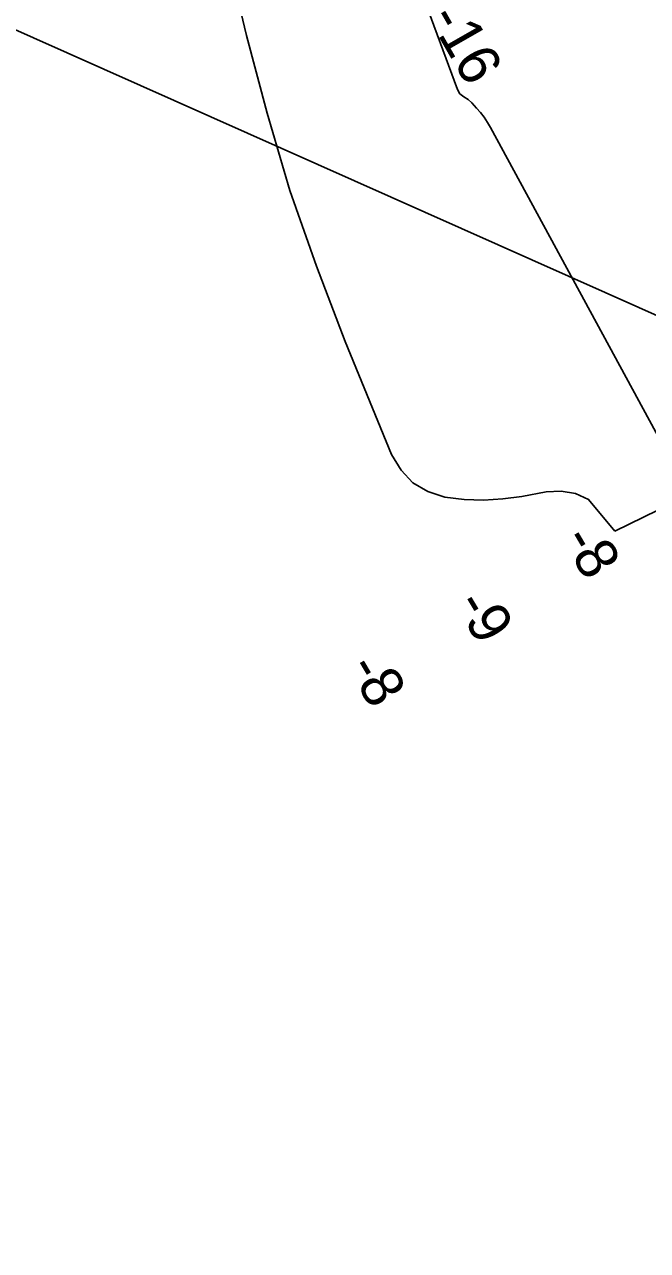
# Model space of a CAD drawing. Extents: x 3972907 to 3994831, y 172639 to 190852.
# Drawn here: x 3982193 to 3982691, y 184038 to 185019 of the extents above; entities that cross this region are included whole.
import ezdxf

# ---------------------------------------------------------------- set-up
doc = ezdxf.new("R2010")
doc.units = 0
for name, color, linetype in [('V-RIVR-JETY', 7, 'Continuous'), ('V-RIVR-RANG', 7, 'Continuous'), ('V-TOPO-DPTH', 7, 'Continuous'), ('V-TOPO-MINR', 7, 'Continuous')]:
    doc.layers.add(name, color=color, linetype=linetype)

msp = doc.modelspace()

# ---------------------------------------------------------------- linework, layer by layer
at = {"layer": 'V-RIVR-JETY'}
msp.add_spline([(3980663.75, 188142.49), (3980923.3, 187897.84), (3981219.12, 187593.73), (3981381.55, 187411.23), (3981548.76, 187223.47), (3981745.95, 186997.4), (3981995.88, 186703.14), (3982287.95, 186350.33), (3982495.82, 186079.54), (3982762.84, 185654.69), (3982971.02, 185292.43), (3983111.24, 185037.47), (3983200.02, 184881.79), (3983229.93, 184826.38)], degree=3, dxfattribs=at)
at = {"layer": 'V-RIVR-RANG'}
msp.add_lwpolyline([(3982021.28, 185087.72), (3990774.16, 181190.72)], dxfattribs=at)
at = {"layer": 'V-TOPO-DPTH'}
for points in [[(3982299.91, 185303.54), (3982370.1, 185010.32), (3982386.54, 184948.03), (3982404.87, 184886.34), (3982426.03, 184825.57), (3982449.07, 184765.41), (3982486.14, 184674.94), (3982493.72, 184662.53), (3982503.07, 184652.35), (3982515.08, 184645.5), (3982528.86, 184640.87), (3982544.28, 184639.14), (3982559.69, 184638.49), (3982575.08, 184639.45), (3982590.47, 184641.5), (3982609.81, 184645.12), (3982621.84, 184645.56), (3982633.24, 184643.88), (3982643.7, 184639.02), (3982664.77, 184613.75)], [(3982664.77, 184613.75), (3983207.36, 184878.75)]]:
    msp.add_lwpolyline(points, dxfattribs=at)
at = {"layer": 'V-TOPO-MINR'}
for points in [[(3982299.91, 185303.54), (3982370.1, 185010.32), (3982386.54, 184948.03), (3982404.87, 184886.34), (3982426.03, 184825.57), (3982449.07, 184765.41), (3982486.14, 184674.94), (3982493.72, 184662.53), (3982503.07, 184652.35), (3982515.08, 184645.5), (3982528.86, 184640.87), (3982544.28, 184639.14), (3982559.69, 184638.49), (3982575.08, 184639.45), (3982590.47, 184641.5), (3982609.81, 184645.12), (3982621.84, 184645.56), (3982633.24, 184643.88), (3982643.7, 184639.02), (3982664.77, 184613.75)], [(3982510.96, 185043.07), (3982538.86, 184967.03), (3982540.84, 184963.67), (3982543.89, 184961.24), (3982547.3, 184959.03), (3982550.3, 184956.3), (3982554.12, 184952.21), (3982557.28, 184948.56), (3982560.25, 184944.76), (3982562.91, 184940.75), (3982565.37, 184936.6), (3982716.34, 184658.45)]]:
    msp.add_lwpolyline(points, dxfattribs=at)

# ---------------------------------------------------------------- texts
at = {"layer": 'V-RIVR-RANG'}
for s, rotation, p in [('-16', 299.78, (3982515.2, 185024.32)), ('-8', 300.73833, (3982621.91, 184606.92)), ('-9', 300.73833, (3982536.29, 184555.26)), ('-8', 300.73833, (3982450.26, 184504.28))]:
    msp.add_text(s, height=33.5, rotation=rotation, dxfattribs=at).set_placement(p)

doc.saveas('drawing.dxf')
